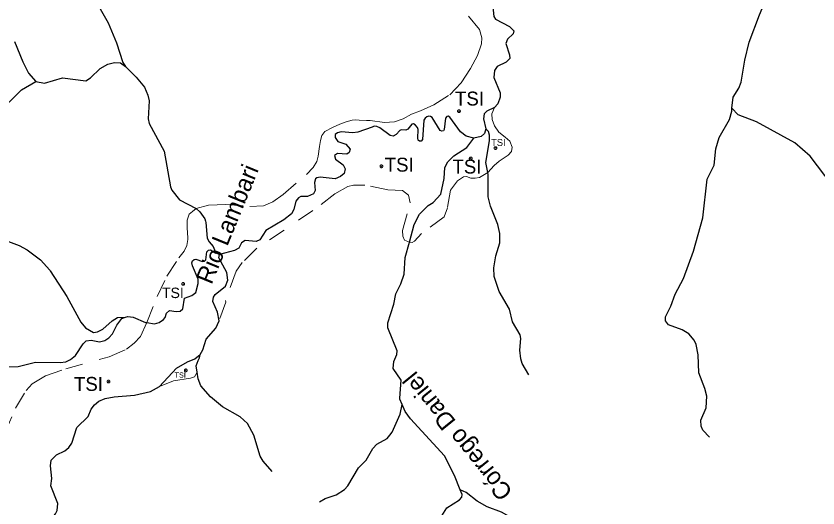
# Model space of a CAD drawing. Extents: x 473.9 to 500, y 7733.1 to 7760.8.
# Drawn here: x 476.875 to 481.483, y 7748.406 to 7751.231 of the extents above; entities that cross this region are included whole.
import ezdxf
from ezdxf.enums import TextEntityAlignment as Align

# ---------------------------------------------------------------- set-up
doc = ezdxf.new("R2010")
doc.units = 0
doc.header["$LTSCALE"] = 0.032
doc.header["$PDMODE"] = 32
doc.header["$PDSIZE"] = 0.016
doc.linetypes.add('SHORT_DASHED', pattern=[2.7, 1.5, -1.2])
doc.layers.add('21', color=7, linetype='SHORT_DASHED', lineweight=13)
doc.layers.add('7', color=7, linetype='Continuous', lineweight=25)
doc.layers.add('61', color=7, linetype='Continuous')

msp = doc.modelspace()

# ---------------------------------------------------------------- linework, layer by layer
at = {"layer": '21'}
for points in [[(477.91, 7750.1255), (477.9807, 7750.1454), (478.08, 7750.1496), (478.2194, 7750.137), (478.2975, 7750.1412), (478.3503, 7750.1644), (478.4095, 7750.2067), (478.5447, 7750.3207), (478.5827, 7750.3609), (478.6038, 7750.3968), (478.6123, 7750.4264), (478.6186, 7750.4813), (478.6249, 7750.5172), (478.6327, 7750.5447), (478.6502, 7750.5686), (478.693, 7750.592), (478.7363, 7750.6108), (478.7718, 7750.6247), (478.8074, 7750.6325), (478.8279, 7750.6347), (478.8462, 7750.6331), (478.8896, 7750.6314), (478.9107, 7750.6308), (478.9927, 7750.6199), (479.0495, 7750.6238), (479.0999, 7750.6419), (479.1473, 7750.668), (479.2001, 7750.6877), (479.2758, 7750.7216), (479.3685, 7750.7795), (479.4332, 7750.8476), (479.4876, 7750.931), (479.5268, 7751.0042), (479.5493, 7751.0723), (479.5527, 7751.1053), (479.5388, 7751.1545), (479.4658, 7751.2416)], [(479.6248, 7750.7064), (479.6102, 7750.6688), (479.6119, 7750.6381), (479.6238, 7750.6007), (479.6494, 7750.5649), (479.6851, 7750.536), (479.7124, 7750.5122), (479.726, 7750.4781), (479.7226, 7750.4526), (479.7022, 7750.4321), (479.6516, 7750.3973), (479.6223, 7750.3734), (479.5865, 7750.3327)], [(479.5865, 7750.3327), (479.5387, 7750.3044), (479.5132, 7750.301), (479.4877, 7750.3004), (479.4644, 7750.309), (479.4456, 7750.3071), (479.4113, 7750.2844), (479.3724, 7750.2321), (479.354, 7750.1292), (479.3347, 7750.079), (479.2057, 7749.9821), (479.1641, 7749.9378), (479.1522, 7749.9316), (479.1355, 7749.9324)], [(479.1355, 7749.9324), (479.108, 7749.9435), (479.0977, 7749.9673), (479.096, 7749.9997), (479.1393, 7750.1581), (479.1305, 7750.2024), (479.0967, 7750.2293), (479.0112, 7750.2341), (478.8803, 7750.2598), (478.8154, 7750.2607), (478.7826, 7750.2522), (478.7074, 7750.2103), (478.5811, 7750.114), (478.2595, 7749.8974), (478.175, 7749.8159), (478.1404, 7749.7668), (478.0798, 7749.5975), (478.08, 7749.5885), (478.0419, 7749.4813)], [(477.6275, 7749.4709), (477.6871, 7749.6216), (477.742, 7749.7377), (477.8104, 7749.8425), (477.8406, 7749.8815), (477.856, 7749.9137), (477.8634, 7749.9475), (477.8616, 7749.9968), (477.8582, 7750.0056), (477.8582, 7750.0588), (477.8708, 7750.0926), (477.8899, 7750.1095), (477.91, 7750.1255)], [(476.688, 7748.3322), (476.7061, 7748.4194), (476.7376, 7748.5617), (476.7719, 7748.7144), (476.812, 7748.8386), (476.8731, 7748.9789), (476.9333, 7749.0811), (476.9689, 7749.1188), (477.0449, 7749.1653), (477.1611, 7749.2054), (477.4104, 7749.2751), (477.5096, 7749.3174), (477.554, 7749.3533), (477.5899, 7749.3913), (477.6275, 7749.4709)], [(477.6995, 7749.1031), (477.7796, 7749.137), (477.8786, 7749.1518), (477.9, 7749.1601), (477.9162, 7749.1857)]]:
    msp.add_lwpolyline(points, dxfattribs=at)
for p in [(479.4204, 7750.6848), (479.6306, 7750.473), (479.4879, 7750.4138), (478.9748, 7750.3683), (477.8359, 7749.6928), (477.8505, 7749.1964), (477.4072, 7749.132)]:
    msp.add_point(p, dxfattribs=at)
at = {"layer": '7'}
msp.add_line((478.045, 7749.8624), (478.024, 7749.869), dxfattribs=at)
for points in [[(476.9923, 7751.981), (476.9953, 7751.9431), (476.9825, 7751.8958), (476.9825, 7751.8658), (477.0216, 7751.7739), (477.0416, 7751.745), (477.0753, 7751.7155), (477.2056, 7751.6411), (477.2294, 7751.6186), (477.2658, 7751.5552), (477.2936, 7751.4814), (477.3192, 7751.3449), (477.4052, 7751.1928), (477.4526, 7751.0769), (477.4887, 7750.9644), (477.5043, 7750.9412)], [(480.9886, 7750.7029), (480.996, 7750.7656), (481.0276, 7750.8166), (481.042, 7750.8524), (481.0625, 7750.9788), (481.0884, 7751.0822), (481.1481, 7751.2388), (481.1617, 7751.2744), (481.1776, 7751.3301), (481.1839, 7751.3658), (481.1822, 7751.4037), (481.1624, 7751.4388), (481.1528, 7751.4504)], [(479.5925, 7751.3562), (479.6127, 7751.3014), (479.6201, 7751.2279), (479.6296, 7751.214), (479.7113, 7751.1714), (479.7359, 7751.1459), (479.7324, 7751.1289), (479.6997, 7751.0988), (479.6902, 7751.0729), (479.7116, 7751.0091), (479.7131, 7750.9872), (479.6922, 7750.9661), (479.6391, 7750.9408), (479.6249, 7750.9186), (479.6216, 7750.8784), (479.6572, 7750.7901), (479.6564, 7750.765), (479.6435, 7750.7266), (479.6248, 7750.7064)], [(476.8676, 7751.0851), (476.914, 7750.9677), (476.9479, 7750.9032), (476.9897, 7750.8554)], [(476.9897, 7750.8554), (477.0398, 7750.8453), (477.1425, 7750.8765), (477.2764, 7750.8586), (477.3038, 7750.8762), (477.3588, 7750.9303), (477.4027, 7750.9558), (477.4404, 7750.9646), (477.4763, 7750.9622), (477.5043, 7750.9412)], [(477.5043, 7750.9412), (477.5659, 7750.8807), (477.6131, 7750.823), (477.6323, 7750.7767), (477.6399, 7750.7441), (477.6351, 7750.6417), (477.6398, 7750.6149), (477.7264, 7750.4558), (477.7627, 7750.2502), (477.771, 7750.2317), (477.8155, 7750.1753), (477.91, 7750.1255)], [(476.6842, 7750.5651), (476.7179, 7750.6238), (476.7738, 7750.6854), (476.8413, 7750.7418), (476.9068, 7750.8069), (476.9897, 7750.8554)], [(479.6248, 7750.7064), (479.5797, 7750.6849), (479.566, 7750.6702), (479.5615, 7750.6404), (479.5756, 7750.5829)], [(480.8593, 7748.8126), (480.8211, 7748.8538), (480.8118, 7748.8763), (480.811, 7748.911), (480.8407, 7748.9806), (480.8438, 7749.0482), (480.834, 7749.0931), (480.7982, 7749.1819), (480.7957, 7749.2862), (480.7828, 7749.3445), (480.7721, 7749.3706), (480.7406, 7749.4072), (480.7037, 7749.4287), (480.6243, 7749.4586), (480.6066, 7749.4801), (480.6066, 7749.5042), (480.6377, 7749.5652), (480.6634, 7749.6346), (480.7102, 7749.7233), (480.7683, 7749.8811), (480.8213, 7750.0731), (480.8459, 7750.2953), (480.8871, 7750.3741), (480.8968, 7750.4679), (480.9146, 7750.5343), (480.9745, 7750.6368), (480.9888, 7750.6851), (480.9886, 7750.7029)], [(481.6072, 7749.7308), (481.6342, 7749.7625), (481.7055, 7749.8202), (481.738, 7749.86), (481.756, 7749.8936), (481.7691, 7749.9424), (481.7723, 7749.9987), (481.7538, 7750.0866), (481.7386, 7750.1187), (481.6887, 7750.179), (481.6054, 7750.2275), (481.5656, 7750.2604), (481.4385, 7750.4261), (481.3495, 7750.5038), (481.1301, 7750.6238), (481.024, 7750.6645), (480.9886, 7750.7029)], [(479.5053, 7750.5303), (479.4626, 7750.5405), (479.4291, 7750.5667), (479.3686, 7750.6501), (479.3576, 7750.6556), (479.3502, 7750.6542), (479.3423, 7750.6455), (479.3353, 7750.5791), (479.3313, 7750.5716), (479.3224, 7750.5699), (479.313, 7750.5746), (479.2663, 7750.6479), (479.2574, 7750.6547), (479.2466, 7750.6562), (479.2366, 7750.652), (479.2268, 7750.6455), (479.2193, 7750.633), (479.2112, 7750.5224), (479.2033, 7750.5129), (479.1934, 7750.5118), (479.1865, 7750.5185), (479.1846, 7750.5297), (479.1865, 7750.5793), (479.1815, 7750.5916), (479.1685, 7750.6064), (479.1589, 7750.6119), (479.1493, 7750.6095), (479.1263, 7750.5807), (479.1144, 7750.5765), (479.088, 7750.5772), (479.0801, 7750.5736), (479.059, 7750.5508), (479.0415, 7750.5414), (479.0244, 7750.5447), (478.9657, 7750.5899), (478.9483, 7750.5966), (478.9341, 7750.5981), (478.9212, 7750.5935), (478.8397, 7750.5647), (478.8101, 7750.5602), (478.7435, 7750.5668), (478.7226, 7750.5606), (478.709, 7750.5507), (478.7089, 7750.5347), (478.7254, 7750.5116), (478.7698, 7750.4948), (478.7947, 7750.466), (478.7899, 7750.447), (478.7763, 7750.4381), (478.7218, 7750.4411), (478.7053, 7750.4305), (478.712, 7750.4089), (478.7548, 7750.3766), (478.7659, 7750.3533), (478.7603, 7750.3272), (478.7399, 7750.3106), (478.709, 7750.2973), (478.6233, 7750.3065), (478.604, 7750.3023), (478.5956, 7750.2968), (478.5901, 7750.2758), (478.5943, 7750.2286), (478.5855, 7750.2105), (478.5505, 7750.1942), (478.5112, 7750.1949), (478.4986, 7750.1882), (478.4837, 7750.1677), (478.4723, 7750.1195), (478.4576, 7750.0961), (478.4138, 7750.0618), (478.3111, 7750.0003), (478.2762, 7749.9458), (478.2543, 7749.9367), (478.1923, 7749.943), (478.1711, 7749.9293), (478.1556, 7749.8992), (478.1312, 7749.8844), (478.045, 7749.8624)], [(479.5756, 7750.5829), (479.5678, 7750.5563), (479.5489, 7750.5393), (479.5053, 7750.5303)], [(479.5865, 7750.3327), (479.574, 7750.3897), (479.5965, 7750.5138), (479.5965, 7750.547), (479.5908, 7750.568), (479.5756, 7750.5829)], [(479.1355, 7749.9324), (479.1626, 7750.0335), (479.1934, 7750.0942), (479.2442, 7750.1436), (479.272, 7750.1611), (479.3157, 7750.2084), (479.3349, 7750.2979), (479.339, 7750.3613), (479.3571, 7750.3945), (479.3911, 7750.4283), (479.4663, 7750.4764), (479.5053, 7750.5303)], [(476.4075, 7750.4134), (476.4239, 7750.3892), (476.4375, 7750.3474), (476.467, 7750.2904), (476.5392, 7750.1926), (476.5622, 7750.1615), (476.6132, 7750.0627), (476.6535, 7750.0157), (476.6933, 7749.9891), (476.8936, 7749.9129), (476.9385, 7749.889), (477.0156, 7749.8307), (477.0689, 7749.7713), (477.0708, 7749.7683), (477.1668, 7749.62), (477.2475, 7749.4731), (477.2754, 7749.4402), (477.3213, 7749.4148), (477.3441, 7749.4173), (477.3739, 7749.4339), (477.4269, 7749.4809), (477.4592, 7749.4997), (477.5049, 7749.5012)], [(479.8211, 7749.17), (479.784, 7749.2366), (479.7759, 7749.2625), (479.7703, 7749.3128), (479.7759, 7749.3793), (479.7712, 7749.3998), (479.728, 7749.476), (479.7101, 7749.5478), (479.6518, 7749.6495), (479.622, 7749.7353), (479.6203, 7749.785), (479.6325, 7749.855), (479.6556, 7749.9296), (479.6557, 7749.9822), (479.6446, 7750.0348), (479.6009, 7750.1394), (479.5883, 7750.1923), (479.589, 7750.3214), (479.5865, 7750.3327)], [(477.91, 7750.1255), (477.9324, 7750.107), (477.9597, 7750.0661), (477.9636, 7750.0524), (477.9654, 7750.046), (477.9734, 7749.9551), (477.9846, 7749.9343), (478.0077, 7749.9086), (478.024, 7749.869)], [(479.0935, 7749.0014), (479.0806, 7749.0309), (479.081, 7749.0365), (479.0879, 7749.1402), (479.0431, 7749.2067), (479.0463, 7749.2469), (479.0644, 7749.2869), (479.0646, 7749.3084), (479.011, 7749.4401), (479.0116, 7749.469), (479.0455, 7749.5773), (479.0577, 7749.6367), (479.0865, 7749.6925), (479.1049, 7749.749), (479.1121, 7749.8449), (479.1355, 7749.9324)], [(477.6275, 7749.4709), (477.6707, 7749.4646), (477.6986, 7749.4722), (477.7234, 7749.4892), (477.7326, 7749.4999), (477.7401, 7749.5253), (477.7563, 7749.541), (477.7964, 7749.5346), (477.8193, 7749.5372), (477.8333, 7749.5507), (477.8435, 7749.6112), (477.8848, 7749.6269), (477.9082, 7749.6443), (477.9228, 7749.6952), (477.9225, 7749.7198), (477.8893, 7749.7964), (477.8861, 7749.8147), (477.8898, 7749.8262), (477.8988, 7749.8336), (477.909, 7749.8349), (477.9467, 7749.8212), (477.9585, 7749.8239), (477.966, 7749.8305), (477.9724, 7749.8773), (477.9812, 7749.8862), (477.9926, 7749.8889), (478.024, 7749.869)], [(478.0419, 7749.4813), (478.0326, 7749.5311), (478.0066, 7749.5916), (478.01, 7749.6178), (478.0189, 7749.6326), (478.0785, 7749.6793), (478.0921, 7749.7146), (478.0862, 7749.7593), (478.0415, 7749.8436), (478.045, 7749.8624)], [(476.8264, 7749.2174), (476.8878, 7749.218), (476.9877, 7749.2441), (477.1292, 7749.2416), (477.1611, 7749.2458), (477.1887, 7749.2586), (477.2174, 7749.2824), (477.261, 7749.3493), (477.2781, 7749.3656), (477.3064, 7749.369), (477.3552, 7749.3611), (477.3861, 7749.3673), (477.4088, 7749.3826), (477.4294, 7749.4057), (477.4552, 7749.4555), (477.484, 7749.4934), (477.5049, 7749.5012)], [(477.5049, 7749.5012), (477.5188, 7749.5064), (477.5485, 7749.5021), (477.6196, 7749.4721), (477.6275, 7749.4709)], [(477.9331, 7749.2882), (477.948, 7749.315), (477.9671, 7749.3748), (478.0233, 7749.4391), (478.0419, 7749.4813)], [(477.6995, 7749.1031), (477.7982, 7749.2097), (477.8611, 7749.2459), (477.9034, 7749.2622), (477.9331, 7749.2882)], [(477.9162, 7749.1857), (477.9108, 7749.2234), (477.9216, 7749.2523), (477.9295, 7749.2693), (477.9331, 7749.2882)], [(478.3472, 7748.6165), (478.2962, 7748.675), (478.2783, 7748.7042), (478.2426, 7748.8237), (478.2045, 7748.8918), (478.1625, 7748.9296), (478.0622, 7748.9862), (477.9923, 7749.044), (477.9381, 7749.1074), (477.9215, 7749.148), (477.9162, 7749.1857)], [(477.0598, 7748.3191), (477.1014, 7748.372), (477.1112, 7748.3924), (477.1162, 7748.4327), (477.0763, 7748.5341), (477.082, 7748.5759), (477.0739, 7748.6491), (477.0778, 7748.6816), (477.1081, 7748.7106), (477.1561, 7748.7339), (477.1794, 7748.7533), (477.1959, 7748.7781), (477.2244, 7748.8682), (477.2903, 7748.9318), (477.3071, 7748.9735), (477.3259, 7748.9989), (477.3517, 7749.0202), (477.3885, 7749.0348), (477.4395, 7749.0451), (477.5553, 7749.0548), (477.6476, 7749.0748), (477.6995, 7749.1031)], [(478.6185, 7748.4406), (478.6516, 7748.4613), (478.7154, 7748.4817), (478.7621, 7748.5116), (478.7828, 7748.5331), (478.8441, 7748.6368), (478.8877, 7748.6806), (478.9261, 7748.7477), (478.9482, 7748.7729), (479.0083, 7748.8061), (479.0227, 7748.8243), (479.0362, 7748.8413), (479.0829, 7748.9443), (479.0935, 7749.0014)], [(479.4278, 7748.51), (479.3946, 7748.5931), (479.3373, 7748.706), (479.1424, 7748.9178), (479.1116, 7748.9603), (479.0935, 7749.0014)], [(478.9839, 7747.5805), (479.0851, 7747.7324), (479.1095, 7747.7805), (479.1456, 7747.8769), (479.176, 7747.9985), (479.2935, 7748.3153), (479.3509, 7748.4069), (479.4226, 7748.4528), (479.4367, 7748.4688), (479.439, 7748.4833), (479.4278, 7748.51)], [(479.8343, 7748.2586), (479.7962, 7748.2948), (479.7729, 7748.3169), (479.7354, 7748.3421), (479.6641, 7748.3822), (479.5821, 7748.4132), (479.5259, 7748.4455), (479.4621, 7748.4945), (479.4278, 7748.51)]]:
    msp.add_lwpolyline(points, dxfattribs=at)

# ---------------------------------------------------------------- texts
at = {"layer": '61'}
for height, p in [(0.08, (479.4809, 7750.7174)), (0.04, (479.6467, 7750.4853)), (0.08, (479.0769, 7750.3377)), (0.08, (479.4664, 7750.3268)), (0.06, (477.7769, 7749.6117)), (0.08, (477.2916, 7749.0786)), (0.03, (477.8189, 7749.1546))]:
    msp.add_text('TSI', height=height, dxfattribs=at).set_placement(p, align=Align.CENTER)
for s, rotation, p in [('Rio Lambari', 67.711, (478.1354, 7750.0184)), ('Córrego Daniel', 128.977, (479.4517, 7748.8491))]:
    msp.add_text(s, height=0.1, rotation=rotation, dxfattribs=at).set_placement(p, align=Align.CENTER)

doc.saveas('drawing.dxf')
